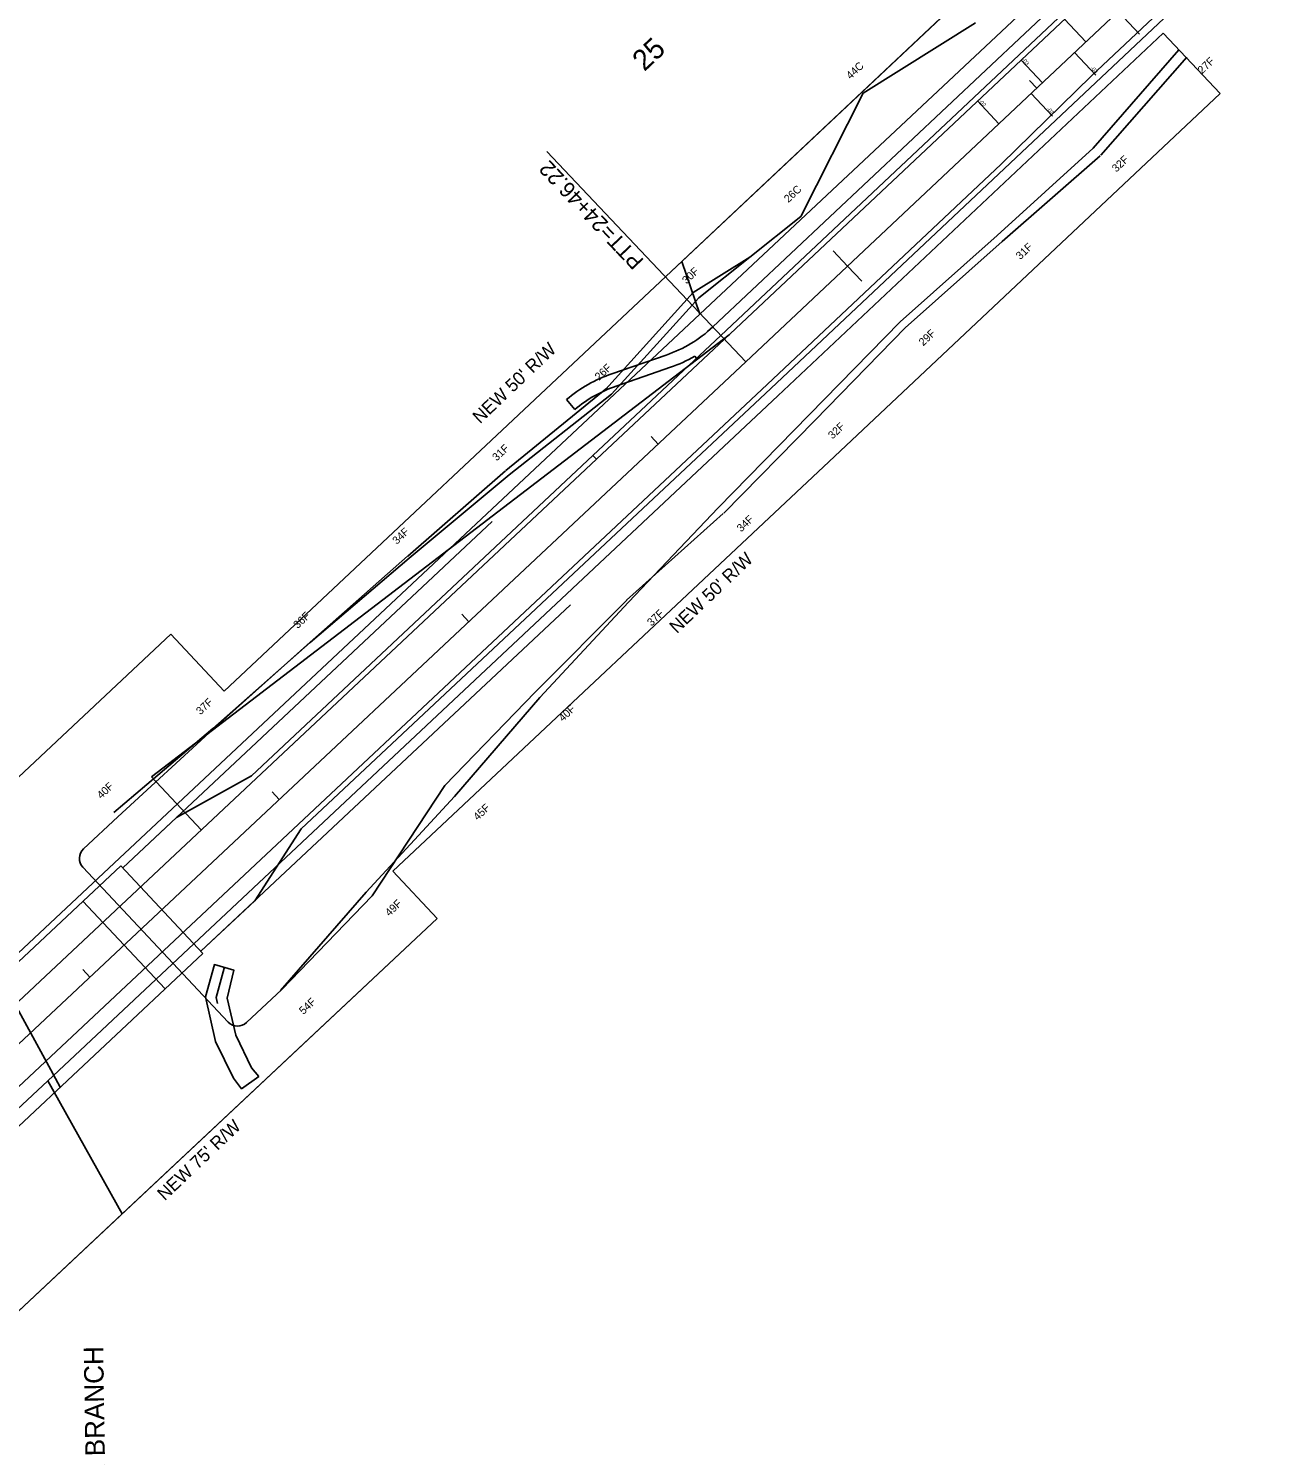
# Model space of a CAD drawing. Extents: x 1623239 to 1625698, y 1118659 to 1120751.
# Drawn here: x 1624403 to 1624877, y 1119484 to 1120033 of the extents above; entities that cross this region are included whole.
import ezdxf

# ---------------------------------------------------------------- set-up
doc = ezdxf.new("R2010")
doc.units = 0
for name, color, linetype in [('BR_CONCRETE', 7, 'Continuous'), ('Default', 7, 'Continuous'), ('RD_EV_JW', 7, 'Continuous'), ('RD_HC_Cl', 7, 'Continuous'), ('RD_HC_Data', 7, 'Continuous'), ('RD_HC_Data_Tic', 7, 'Continuous'), ('RD_HC_TX_Sta50', 7, 'Continuous'), ('RD_PD_ALT1_TX', 7, 'Continuous'), ('RD_PD_BOC', 7, 'Continuous'), ('RD_PD_CstnLmt', 7, 'Continuous'), ('RD_PD_CstnLmt_TX', 7, 'Continuous'), ('RD_PD_DR_ErosCtrl', 7, 'Continuous'), ('RD_PD_Final_TrvlWay', 7, 'Continuous'), ('RD_PD_GR', 7, 'Continuous'), ('RD_PD_PaintMed', 7, 'Continuous'), ('RD_PD_PaveShd', 7, 'Continuous'), ('RD_PD_RW', 7, 'Continuous'), ('RD_PD_RW_TX', 7, 'Continuous'), ('RD_PD_SW', 7, 'Continuous'), ('RD_QTY_Clear_Grub', 7, 'Continuous'), ('RD_Sketch8', 7, 'Continuous')]:
    doc.layers.add(name, color=color, linetype=linetype)

msp = doc.modelspace()

# ---------------------------------------------------------------- linework, layer by layer
at = {"layer": 'BR_CONCRETE'}
for p, q in [((1624335.9, 1119615.36), (1624438.01, 1119711.13)), ((1624438.01, 1119711.13), (1624469.65, 1119677.4)), ((1624423.43, 1119697.45), (1624455.06, 1119663.72)), ((1624367.53, 1119581.63), (1624469.65, 1119677.4))]:
    msp.add_line(p, q, dxfattribs=at)
at = {"layer": 'Default'}
for points in [[(1624477.79, 1119671.76), (1624474.75, 1119660.37), (1624475.28, 1119658.09)], [(1624391.81, 1119667.8), (1624411.15, 1119632.51), (1624414.74, 1119625.9)]]:
    msp.add_lwpolyline(points, dxfattribs=at)
at = {"layer": 'RD_EV_JW'}
msp.add_lwpolyline([(1624491.11, 1119630.04), (1624484.56, 1119625.28), (1624481.37, 1119629.42), (1624474.52, 1119643.47), (1624470.63, 1119660.66), (1624474.04, 1119673.1), (1624481.57, 1119670.92), (1624478.94, 1119660.21), (1624482.3, 1119645.88), (1624488.37, 1119633.36)], close=True, dxfattribs=at)
at = {"layer": 'RD_HC_Cl'}
for p, q in [((1624678.65, 1119905.11), (1625124.67, 1120324.94)), ((1624678.65, 1119905.11), (1624870.49, 1120085.68)), ((1623937.25, 1119209.79), (1624678.65, 1119905.11)), ((1623937.25, 1119209.79), (1624678.65, 1119905.11))]:
    msp.add_line(p, q, dxfattribs=at)
at = {"layer": 'RD_HC_Data'}
msp.add_line((1624678.65, 1119905.11), (1624601.99, 1119986.14), dxfattribs=at)
at = {"layer": 'RD_HC_Data_Tic'}
for p, q in [((1624790.63, 1120010.51), (1624787.89, 1120013.42)), ((1624717.81, 1119941.97), (1624712.33, 1119947.8)), ((1624717.81, 1119941.97), (1624723.3, 1119936.15)), ((1624644.94, 1119873.49), (1624642.2, 1119876.41)), ((1624572, 1119805.09), (1624569.26, 1119808)), ((1624499.06, 1119736.68), (1624496.32, 1119739.6)), ((1624426.12, 1119668.27), (1624423.38, 1119671.19))]:
    msp.add_line(p, q, dxfattribs=at)
at = {"layer": 'RD_PD_ALT1_TX'}
for p, q in [((1624821.94, 1120039.98), (1624830.17, 1120031.25)), ((1624801.34, 1120037.07), (1624809.56, 1120028.33)), ((1624805.19, 1120024.22), (1624813.42, 1120015.48)), ((1624784.59, 1120021.31), (1624792.81, 1120012.57)), ((1624767.84, 1120005.54), (1624776.07, 1119996.8)), ((1624788.45, 1120008.46), (1624796.67, 1119999.72))]:
    msp.add_line(p, q, dxfattribs=at)
at = {"layer": 'RD_PD_BOC'}
for p, q in [((1624669.06, 1119915.31), (1624815.54, 1120053.18)), ((1624619.77, 1119869.08), (1624669.07, 1119915.32)), ((1624621.14, 1119867.62), (1624619.77, 1119869.08))]:
    msp.add_line(p, q, dxfattribs=at)
at = {"layer": 'RD_PD_CstnLmt'}
for p, q in [((1624723.78, 1120008.58), (1624767.03, 1120035.59)), ((1624812.38, 1119987.4), (1624845.41, 1120025.27)), ((1624699.82, 1119961.09), (1624723.78, 1120008.58)), ((1624775.4, 1119953.74), (1624812.38, 1119987.4)), ((1624660.62, 1119929.79), (1624699.82, 1119961.09)), ((1624738.03, 1119920.49), (1624775.4, 1119953.74)), ((1624626.98, 1119892.65), (1624660.62, 1119929.79)), ((1624703.1, 1119884.66), (1624738.03, 1119920.49)), ((1624587.51, 1119861.63), (1624626.98, 1119892.65)), ((1624667.99, 1119848.91), (1624703.1, 1119884.66)), ((1624549.07, 1119829.53), (1624587.51, 1119861.63)), ((1624633.45, 1119812.65), (1624667.99, 1119848.91)), ((1624510.92, 1119797.12), (1624549.07, 1119829.53)), ((1624599.36, 1119775.91), (1624633.45, 1119812.65)), ((1624473.5, 1119763.93), (1624510.92, 1119797.12)), ((1624566.51, 1119737.85), (1624599.36, 1119775.91)), ((1624435.3, 1119731.57), (1624473.5, 1119763.93)), ((1624532.54, 1119700.97), (1624566.51, 1119737.85)), ((1624499.46, 1119663.15), (1624532.54, 1119700.97))]:
    msp.add_line(p, q, dxfattribs=at)
at = {"layer": 'RD_PD_DR_ErosCtrl'}
for p, q in [((1624815.3, 1119984.72), (1624848.49, 1120022.4)), ((1624777.38, 1119951.48), (1624815.02, 1119984.44)), ((1624740.03, 1119918.25), (1624777.4, 1119951.5)), ((1624658.39, 1119931.8), (1624680.22, 1119945.44)), ((1624624.75, 1119894.66), (1624658.39, 1119931.8)), ((1624705.25, 1119882.56), (1624740.18, 1119918.4)), ((1624586.26, 1119863.28), (1624625.08, 1119894.97)), ((1624670.13, 1119846.81), (1624705.24, 1119882.55)), ((1624548.48, 1119830.32), (1624586.18, 1119863.21)), ((1624632.74, 1119813.31), (1624669.99, 1119846.68)), ((1624510.95, 1119797.22), (1624548.46, 1119830.31)), ((1624597.58, 1119777.96), (1624632.87, 1119813.42)), ((1624473.71, 1119763.8), (1624510.93, 1119797.21)), ((1624562.81, 1119742), (1624597.61, 1119777.99)), ((1624436.83, 1119729.99), (1624473.69, 1119763.78)), ((1624534.78, 1119699.55), (1624562.81, 1119742)), ((1624423.67, 1119717.65), (1624436.83, 1119729.99)), ((1624423.45, 1119710.59), (1624479.36, 1119650.97)), ((1624500.03, 1119663.5), (1624534.78, 1119699.55)), ((1624486.43, 1119650.74), (1624500.03, 1119663.5))]:
    msp.add_line(p, q, dxfattribs=at)
for centre, start, end in [((1624427.09, 1119714.01), 133.1627, 223.1627), ((1624483.01, 1119654.39), 223.1627, 313.1627)]:
    msp.add_arc(centre, 5, start, end, dxfattribs=at)
at = {"layer": 'RD_PD_Final_TrvlWay'}
for p, q in [((1624670.43, 1119913.85), (1624816.91, 1120051.72)), ((1624621.14, 1119867.62), (1624670.43, 1119913.85))]:
    msp.add_line(p, q, dxfattribs=at)
at = {"layer": 'RD_PD_GR'}
for p, q in [((1624438.78, 1119710.31), (1624581.02, 1119843.71)), ((1624611.12, 1119811.61), (1624468.88, 1119678.22))]:
    msp.add_line(p, q, dxfattribs=at)
at = {"layer": 'RD_PD_PaintMed'}
for p, q in [((1624678.65, 1119905.11), (1624844.95, 1120061.65)), ((1624811.67, 1120015.21), (1624852.49, 1120053.64)), ((1624777.01, 1119981.21), (1624811.67, 1120015.21)), ((1624686.87, 1119896.36), (1624777.01, 1119981.21)), ((1623963.49, 1119234.4), (1624678.65, 1119905.11)), ((1623971.7, 1119225.65), (1624686.87, 1119896.36)), ((1624336.32, 1119600.51), (1624621.14, 1119867.62))]:
    msp.add_line(p, q, dxfattribs=at)
at = {"layer": 'RD_PD_PaveShd'}
for p, q in [((1624688.24, 1119894.91), (1624854.55, 1120051.45)), ((1624507.46, 1119725.36), (1624688.23, 1119894.9)), ((1624488.31, 1119745.79), (1624619.77, 1119869.08)), ((1624459.49, 1119729.73), (1624488.31, 1119745.79)), ((1624438.78, 1119710.31), (1624459.49, 1119729.73)), ((1624489.59, 1119697.64), (1624507.46, 1119725.36)), ((1624468.88, 1119678.22), (1624489.59, 1119697.64))]:
    msp.add_line(p, q, dxfattribs=at)
at = {"layer": 'RD_PD_RW'}
for p, q in [((1624647.87, 1119937.94), (1624796.19, 1120077.55)), ((1624839.38, 1120031.68), (1624861.31, 1120008.37)), ((1624712.85, 1119868.64), (1624861.31, 1120008.37)), ((1624477.76, 1119778.39), (1624647.87, 1119937.93)), ((1624542.74, 1119709.1), (1624712.85, 1119868.64)), ((1624245.7, 1119601.9), (1624457.23, 1119800.28)), ((1624457.23, 1119800.28), (1624477.76, 1119778.39)), ((1624542.74, 1119709.1), (1624559.84, 1119690.86)), ((1624348.31, 1119492.48), (1624559.84, 1119690.86))]:
    msp.add_line(p, q, dxfattribs=at)
at = {"layer": 'RD_PD_SW'}
for p, q in [((1624665.98, 1119918.59), (1624825.51, 1120068.75)), ((1624665.93, 1119918.54), (1624666, 1119918.6)), ((1624648.01, 1119907.74), (1624627.1, 1119900.54)), ((1624659.02, 1119907.26), (1624659.7, 1119906.53)), ((1624649.64, 1119903.01), (1624628.72, 1119895.81)), ((1624612.84, 1119886.81), (1624609.62, 1119890.64))]:
    msp.add_line(p, q, dxfattribs=at)
for centre, radius, start, end in [((1624631.73, 1119955.01), 50, 289.0024, 313.1627), ((1624631.73, 1119955.01), 55, 289.0024, 299.7507), ((1624645.01, 1119848.53), 55, 109.0024, 130.0403), ((1624645.01, 1119848.53), 50, 109.0024, 130.0403)]:
    msp.add_arc(centre, radius, start, end, dxfattribs=at)
at = {"layer": 'RD_QTY_Clear_Grub'}
for p, q in [((1624796.19, 1120077.55), (1624654.03, 1119943.73)), ((1624660.93, 1119923.47), (1624807.12, 1120060.5)), ((1624861.31, 1120008.37), (1624839.38, 1120031.68)), ((1624712.85, 1119868.64), (1624861.31, 1120008.37)), ((1624654.03, 1119943.73), (1624647.87, 1119937.94)), ((1624660.93, 1119923.47), (1624654.03, 1119943.73)), ((1624654.03, 1119943.73), (1624660.93, 1119923.47)), ((1624647.87, 1119937.94), (1624477.76, 1119778.39)), ((1624394.42, 1119673.64), (1624660.93, 1119923.47)), ((1624542.74, 1119709.1), (1624712.85, 1119868.64)), ((1624457.23, 1119800.28), (1624378.88, 1119726.79)), ((1624477.76, 1119778.39), (1624457.23, 1119800.28)), ((1624559.84, 1119690.86), (1624542.74, 1119709.1)), ((1624438.51, 1119577.07), (1624559.84, 1119690.86)), ((1624409.91, 1119628.39), (1624066.43, 1119306.26)), ((1624438.51, 1119577.07), (1624409.91, 1119628.39)), ((1624409.91, 1119628.39), (1624438.51, 1119577.07)), ((1624348.31, 1119492.48), (1624438.51, 1119577.07))]:
    msp.add_line(p, q, dxfattribs=at)
msp.add_lwpolyline([(1624839.38, 1120031.68), (1624691.01, 1119892.02), (1624409.91, 1119628.39)], dxfattribs=at)
at = {"layer": 'RD_Sketch8'}
for p, q in [((1624449.81, 1119745.33), (1624672.18, 1119915.49)), ((1624468.97, 1119724.91), (1624449.81, 1119745.33))]:
    msp.add_line(p, q, dxfattribs=at)

# ---------------------------------------------------------------- texts
at = {"layer": 'RD_HC_Data'}
for s, height, rotation, p in [('PTT=24+46.22', 6, 133.4099, (1624639.74, 1119944.23)), ('SUBER BRANCH', 7.5, 90.8976, (1624432.49, 1119446.53))]:
    msp.add_text(s, height=height, rotation=rotation, dxfattribs=at).set_placement(p)
at = {"layer": 'RD_HC_TX_Sta50'}
msp.add_text('25', height=8, rotation=43.2675, dxfattribs=at).set_placement((1624639.6, 1120016.67))
at = {"layer": 'RD_PD_ALT1_TX'}
for s, p in [('-03', (1624784.77, 1120021.28)), ('-03', (1624811.2, 1120018.15)), ('-02', (1624768.23, 1120005.33)), ('-02', (1624794.35, 1120002.35))]:
    msp.add_text(s, height=1.5, rotation=313.2675, dxfattribs=at).set_placement(p)
at = {"layer": 'RD_PD_CstnLmt_TX'}
for s, rotation, p in [('27F', 43.2675, (1624854.32, 1120015.8)), ('44C', 43.2675, (1624718.98, 1120013.68)), ('32F', 43.2675, (1624821.29, 1119977.94)), ('26C', 43.2675, (1624695.02, 1119966.19)), ('31F', 43.2675, (1624784.31, 1119944.27)), ('30F', 43.2675, (1624655.82, 1119934.88)), ('29F', 43.2675, (1624746.94, 1119911.03)), ('26F', 43.1627, (1624622.19, 1119897.75)), ('32F', 43.2675, (1624712.01, 1119875.19)), ('31F', 43.1627, (1624582.73, 1119866.74)), ('34F', 43.1627, (1624676.88, 1119839.43)), ('34F', 43.1627, (1624544.28, 1119834.64)), ('36F', 43.1627, (1624506.14, 1119802.22)), ('37F', 43.1627, (1624642.34, 1119803.17)), ('37F', 43.1627, (1624468.71, 1119769.04)), ('40F', 43.1627, (1624608.25, 1119766.43)), ('40F', 43.1627, (1624430.51, 1119736.67)), ('45F', 43.1627, (1624575.4, 1119728.37)), ('49F', 43.1627, (1624541.44, 1119691.49)), ('54F', 43.1627, (1624508.35, 1119653.67))]:
    msp.add_text(s, height=3, rotation=rotation, dxfattribs=at).set_placement(p)
at = {"layer": 'RD_PD_RW_TX'}
for s, p in [("NEW 50' R/W", (1624576.33, 1119881.07)), ("NEW 50' R/W", (1624652.1, 1119800.28)), ("NEW 75' R/W", (1624454.96, 1119581.96))]:
    msp.add_text(s, height=5, rotation=43.605, dxfattribs=at).set_placement(p)

doc.saveas('drawing.dxf')
